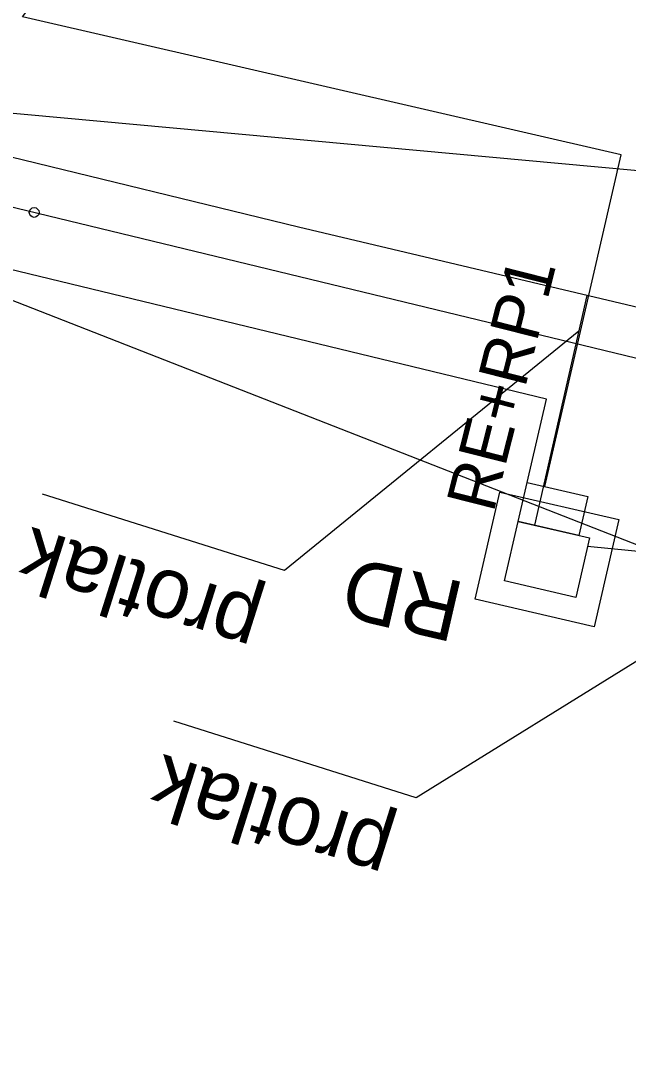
# Model space of a CAD drawing. Extents: x -748315 to -743169, y -1131781 to -1127091.
# Drawn here: x -747628.12 to -747603.24, y -1131732.11 to -1131689.86 of the extents above; entities that cross this region are included whole.
import ezdxf

# ---------------------------------------------------------------- set-up
doc = ezdxf.new("R2010")
doc.units = 0
for name, color, linetype in [('_RD', 7, 'Continuous'), ('_ROZHLED_trojuhelník', 7, 'Continuous'), ('_TRASA_vedení kabelu_CEZ', 7, 'Continuous'), ('_Zabezpečovací zařízení_trasa', 7, 'Continuous'), ('Nový stav', 7, 'Continuous'), ('POP_KOLEJ', 7, 'Continuous'), ('SMEROVE_A_VYSKOVE_VYROVNANI', 7, 'Continuous')]:
    doc.layers.add(name, color=color, linetype=linetype)

# ---------------------------------------------------------------- blocks, each defined once
blk = doc.blocks.new('AeccTickCircle')
blk.add_circle((0, 0), 0.5)

msp = doc.modelspace()

# ---------------------------------------------------------------- linework, layer by layer
msp.add_lwpolyline([(-747607.376, -1131708.78), (-747606.588, -1131705.368), (-747647.265, -1131695.524)])
at = {"layer": '_RD'}
for points in [[(-747609.505, -1131713.555), (-747608.492, -1131709.17), (-747603.621, -1131710.295), (-747604.633, -1131714.68)], [(-747609.505, -1131713.555), (-747608.492, -1131709.17), (-747603.621, -1131710.295), (-747604.633, -1131714.68)], [(-747608.306, -1131712.805), (-747607.743, -1131710.369), (-747604.82, -1131711.045), (-747605.383, -1131713.48)], [(-747608.306, -1131712.805), (-747607.743, -1131710.369), (-747604.82, -1131711.045), (-747605.383, -1131713.48)]]:
    msp.add_lwpolyline(points, close=True, dxfattribs=at)
at = {"layer": '_ROZHLED_trojuhelník'}
msp.add_lwpolyline([(-747594.358, -1131696.788), (-747654.001, -1131691.323), (-747593.974, -1131714.814), (-747534.332, -1131720.284)], close=True, dxfattribs=at)
at = {"layer": '_TRASA_vedení kabelu_CEZ'}
msp.add_lwpolyline([(-747606.661, -1131708.945), (-747603.525, -1131695.366), (-747628.041, -1131689.704), (-747599.968, -1131653.349), (-747599.823, -1131650.348), (-747590.152, -1131609.621), (-747577.851, -1131574.826), (-747576.114, -1131566.001), (-747573.02, -1131550.257), (-747574.144, -1131533.397), (-747574.335, -1131530.458), (-747575.576, -1131507.342), (-747576.376, -1131492.518), (-747578.396, -1131453.504)], dxfattribs=at)
msp.add_lwpolyline([(-747607.376, -1131708.78), (-747604.899, -1131709.352), (-747605.267, -1131710.943), (-747607.743, -1131710.371)], close=True, dxfattribs=at)
at = {"layer": '_Zabezpečovací zařízení_trasa'}
for p, q in [((-747604.936, -1131701.113), (-747607.078, -1131710.523)), ((-747590.628, -1131712.828), (-747604.902, -1131711.398))]:
    msp.add_line(p, q, dxfattribs=at)
msp.add_lwpolyline([(-747299.39, -1131774.358), (-747312.964, -1131771.536), (-747335.194, -1131765.862), (-747431.496, -1131743.033), (-747485.589, -1131729.823), (-747529.872, -1131718.897), (-747616.745, -1131698.315), (-747822.016, -1131648.41), (-747861.482, -1131639.038), (-748013.304, -1131601.999), (-748116.903, -1131577.077), (-748210.219, -1131554.485), (-748277.301, -1131538.228)], dxfattribs=at)
at = {"layer": 'Nový stav'}
for p, q in [((-747605.27, -1131702.58), (-747617.314, -1131712.384)), ((-747589.393, -1131707.724), (-747611.929, -1131721.686)), ((-747617.314, -1131712.384), (-747627.223, -1131709.25)), ((-747611.929, -1131721.686), (-747621.838, -1131718.551))]:
    msp.add_line(p, q, dxfattribs=at)
at = {"layer": 'SMEROVE_A_VYSKOVE_VYROVNANI'}
msp.add_lwpolyline([(-747648.511, -1131692.65), (-747601.65, -1131703.991)], dxfattribs=at)

# ---------------------------------------------------------------- block references
at = {"layer": 'POP_KOLEJ', "xscale": 0.39999999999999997, "yscale": 0.3999999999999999, "rotation": 166.39613006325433}
msp.add_blockref('AeccTickCircle', (-747627.561, -1131697.72), dxfattribs=at)

# ---------------------------------------------------------------- texts
at = {"layer": '_RD'}
msp.add_text('RD', height=2.5, rotation=166.9979, dxfattribs=at).set_placement((-747609.862, -1131712.894))
at = {"layer": '_TRASA_vedení kabelu_CEZ'}
msp.add_text('RE+RP1', height=2, rotation=75.7809, dxfattribs=at).set_placement((-747608.764, -1131710.06))
at = {"layer": 'Nový stav'}
for p in [(-747618.094, -1131713.615), (-747612.709, -1131722.916)]:
    msp.add_text('protlak', height=2.5, rotation=162.4464, dxfattribs=at).set_placement(p)

doc.saveas('drawing.dxf')
